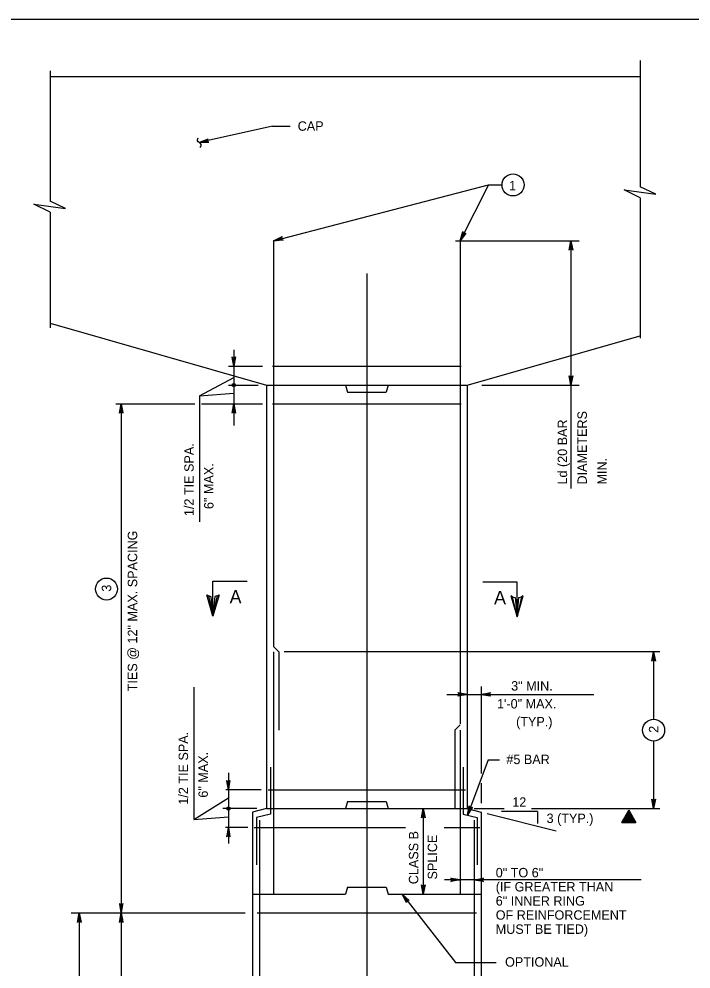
# Model space of a CAD drawing. Extents: x 646165 to 651486, y 296916 to 299292.
# Drawn here: x 650043.7 to 650257.8, y 298380.6 to 298683.3 of the extents above; entities that cross this region are included whole.
import ezdxf

# ---------------------------------------------------------------- set-up
doc = ezdxf.new("R2010")
doc.units = 0
for name, color, linetype in [('1', 7, 'Continuous'), ('2', 7, 'Continuous'), ('50', 7, 'Continuous'), ('51', 7, 'Continuous'), ('52', 7, 'Continuous'), ('53', 7, 'Continuous'), ('54', 7, 'Continuous')]:
    doc.layers.add(name, color=color, linetype=linetype)

msp = doc.modelspace()

# ---------------------------------------------------------------- linework, layer by layer
at = {"layer": '1'}
for p, q in [((650105.44, 298504.11), (650116.37, 298504.11)), ((650105.44, 298493.05), (650105.44, 298504.11)), ((650202.41, 298503.85), (650191.49, 298503.85)), ((650202.41, 298492.78), (650202.41, 298503.85))]:
    msp.add_line(p, q, dxfattribs=at)
for points in [[(650106.92, 298499.47), (650106.07, 298499.23), (650105.44, 298493.05), (650106.92, 298499.47), (650107.43, 298499.8), (650105.44, 298493.05), (650104.89, 298499.22), (650104.05, 298499.45), (650105.44, 298493.05), (650103.49, 298499.8), (650104.05, 298499.45)], [(650200.94, 298499.2), (650201.79, 298498.96), (650202.41, 298492.78), (650200.94, 298499.2), (650200.42, 298499.53), (650202.41, 298492.78), (650202.97, 298498.95), (650203.8, 298499.18), (650202.41, 298492.78), (650204.36, 298499.53), (650203.8, 298499.18)]]:
    msp.add_lwpolyline(points, dxfattribs=at)
at = {"layer": '2'}
msp.add_line((649829.59, 298683.25), (650615.59, 298683.25), dxfattribs=at)
at = {"layer": '50'}
msp.add_line((650154.51, 298602.2), (650154.51, 298236.03), dxfattribs=at)
at = {"layer": '51'}
for p, q in [((650053.58, 298664.97), (650241.62, 298664.97)), ((650053.58, 298586.3), (650122.56, 298566.63)), ((650186.46, 298566.63), (650241.62, 298582.36)), ((650122.56, 298566.63), (650186.46, 298566.63)), ((650122.56, 298566.63), (650122.56, 298431.7)), ((650147.76, 298566.63), (650148.34, 298564.38)), ((650161.26, 298566.63), (650160.68, 298564.38)), ((650186.46, 298566.63), (650186.46, 298431.7)), ((650148.34, 298564.38), (650160.68, 298564.38)), ((650122.56, 298431.7), (650118.06, 298430.58)), ((650122.56, 298431.7), (650186.46, 298431.7)), ((650148.34, 298433.95), (650147.76, 298431.7)), ((650148.34, 298433.95), (650160.68, 298433.95)), ((650160.68, 298433.95), (650161.26, 298431.7)), ((650186.46, 298431.7), (650190.96, 298430.58)), ((650118.06, 298430.58), (650118.06, 298296.63)), ((650190.96, 298430.58), (650190.96, 298296.63)), ((650118.06, 298404.45), (650147.76, 298404.45)), ((650148.34, 298406.7), (650147.76, 298404.45)), ((650148.34, 298406.7), (650160.68, 298406.7)), ((650160.68, 298406.7), (650161.26, 298404.45)), ((650161.26, 298404.45), (650190.96, 298404.45))]:
    msp.add_line(p, q, dxfattribs=at)
at = {"layer": '52'}
for p, q in [((650241.62, 298669.99), (650241.62, 298629.76)), ((650053.58, 298666.75), (650053.58, 298625.21)), ((650124.47, 298649.16), (650101.14, 298643.86)), ((650124.47, 298649.16), (650130.06, 298649.16)), ((650124.81, 298612.63), (650193.25, 298630.39)), ((650193.25, 298630.39), (650184.21, 298612.63)), ((650193.25, 298630.39), (650197.58, 298630.39)), ((650241.62, 298626.25), (650241.62, 298581.59)), ((650053.58, 298621.69), (650053.58, 298584.86)), ((650182.75, 298612.63), (650222.19, 298612.63)), ((650219.55, 298612.63), (650219.55, 298533.69)), ((650112.12, 298577.88), (650112.12, 298553.76)), ((650110.46, 298572.63), (650121.22, 298572.63)), ((650101.17, 298563.18), (650112.12, 298569.05)), ((650110.46, 298566.63), (650119.93, 298566.63)), ((650191.13, 298566.63), (650222.19, 298566.63)), ((650101.17, 298563.18), (650112.12, 298564.02)), ((650101.17, 298563.18), (650101.17, 298523.1)), ((650074.5, 298560.63), (650099.68, 298560.63)), ((650076.27, 298560.63), (650076.27, 298299.7)), ((650101.81, 298560.63), (650121.22, 298560.63)), ((650247.88, 298481.7), (650128.12, 298481.7)), ((650245.88, 298481.7), (650245.88, 298460.2)), ((650099.44, 298470.42), (650099.44, 298428.26)), ((650179.95, 298468.09), (650226.79, 298468.09)), ((650190.96, 298470.58), (650190.96, 298442.92)), ((650245.88, 298453.2), (650245.88, 298431.7)), ((650193.18, 298447.21), (650186.6, 298429.57)), ((650193.18, 298447.21), (650196.79, 298447.21)), ((650110.4, 298443.08), (650110.4, 298420.61)), ((650120.81, 298437.7), (650109.55, 298437.7)), ((650190.96, 298439.77), (650190.96, 298433.48)), ((650099.44, 298428.26), (650110.4, 298435.12)), ((650119.41, 298431.7), (650108.62, 298431.7)), ((650172.49, 298431.7), (650172.49, 298404.45)), ((650188.72, 298431.7), (650198.25, 298431.7)), ((650206.99, 298431.7), (650247.88, 298431.7)), ((650099.44, 298428.26), (650110.4, 298429.1)), ((650192.84, 298430.11), (650214.87, 298424.6)), ((650208.84, 298430.82), (650197.38, 298430.82)), ((650208.84, 298430.82), (650208.84, 298426.99)), ((650116.58, 298425.7), (650109.47, 298425.7)), ((650241.86, 298409.02), (650179.3, 298409.02)), ((650165.77, 298404.45), (650182.77, 298382.66)), ((650060.29, 298398.45), (650115.76, 298398.45)), ((650062.91, 298398.45), (650062.91, 298274.96)), ((650182.77, 298382.66), (650195.67, 298382.66))]:
    msp.add_line(p, q, dxfattribs=at)
for points in [[(650101.14, 298643.86), (650103.92, 298645.07), (650103.83, 298644.97), (650103.74, 298644.86), (650103.7, 298644.75), (650103.66, 298644.64), (650103.67, 298644.54), (650103.68, 298644.44), (650103.71, 298644.34), (650103.75, 298644.25), (650103.83, 298644.17), (650103.91, 298644.08), (650104.04, 298644.03), (650104.17, 298643.98), (650101.14, 298643.86), (650104.04, 298644.03), (650103.91, 298644.08), (650101.14, 298643.86), (650103.83, 298644.17), (650103.75, 298644.25), (650101.14, 298643.86), (650103.71, 298644.34), (650103.68, 298644.44), (650101.14, 298643.86), (650103.67, 298644.54), (650103.66, 298644.64), (650101.14, 298643.86), (650103.7, 298644.75), (650103.74, 298644.86), (650101.14, 298643.86), (650103.83, 298644.97)], [(650241.62, 298626.25), (650236.44, 298628.78), (650246.59, 298627.4), (650241.62, 298629.76)], [(650053.58, 298621.69), (650048.39, 298624.23), (650058.54, 298622.85), (650053.58, 298625.21)], [(650124.81, 298612.63), (650127.56, 298613.92), (650127.38, 298613.71), (650127.31, 298613.49), (650127.33, 298613.29), (650127.41, 298613.1), (650127.58, 298612.94), (650127.84, 298612.84), (650124.81, 298612.63), (650127.58, 298612.94), (650127.41, 298613.1), (650124.81, 298612.63), (650127.33, 298613.29), (650127.31, 298613.49), (650124.81, 298612.63), (650127.38, 298613.71)], [(650184.21, 298612.63), (650185.07, 298615.55), (650185.08, 298615.41), (650185.1, 298615.27), (650185.17, 298615.17), (650185.23, 298615.07), (650185.31, 298615.01), (650185.39, 298614.95), (650185.49, 298614.92), (650185.58, 298614.89), (650185.7, 298614.9), (650185.82, 298614.91), (650185.94, 298614.97), (650186.06, 298615.04), (650184.21, 298612.63), (650185.94, 298614.97), (650185.82, 298614.91), (650184.21, 298612.63), (650185.7, 298614.9), (650185.58, 298614.89), (650184.21, 298612.63), (650185.49, 298614.92), (650185.39, 298614.95), (650184.21, 298612.63), (650185.31, 298615.01), (650185.23, 298615.07), (650184.21, 298612.63), (650185.17, 298615.17), (650185.1, 298615.27), (650184.21, 298612.63), (650185.08, 298615.41)], [(650219.55, 298612.63), (650220.11, 298609.65), (650220.03, 298609.77), (650219.95, 298609.88), (650219.85, 298609.94), (650219.75, 298610), (650219.65, 298610.02), (650219.55, 298610.03), (650219.45, 298610.02), (650219.35, 298610), (650219.25, 298609.94), (650219.15, 298609.88), (650219.07, 298609.77), (650219, 298609.65), (650219.55, 298612.63), (650219.07, 298609.77), (650219.15, 298609.88), (650219.55, 298612.63), (650219.25, 298609.94), (650219.35, 298610), (650219.55, 298612.63), (650219.45, 298610.02), (650219.55, 298610.03), (650219.55, 298612.63), (650219.65, 298610.02), (650219.75, 298610), (650219.55, 298612.63), (650219.85, 298609.94), (650219.95, 298609.88), (650219.55, 298612.63), (650220.03, 298609.77)], [(650112.12, 298572.63), (650111.56, 298575.61), (650111.64, 298575.49), (650111.72, 298575.38), (650111.82, 298575.32), (650111.92, 298575.26), (650112.02, 298575.24), (650112.12, 298575.23), (650112.22, 298575.24), (650112.32, 298575.26), (650112.42, 298575.32), (650112.52, 298575.38), (650112.6, 298575.49), (650112.68, 298575.61), (650112.12, 298572.63), (650112.6, 298575.49), (650112.52, 298575.38), (650112.12, 298572.63), (650112.42, 298575.32), (650112.32, 298575.26), (650112.12, 298572.63), (650112.22, 298575.24), (650112.12, 298575.23), (650112.12, 298572.63), (650112.02, 298575.24), (650111.92, 298575.26), (650112.12, 298572.63), (650111.82, 298575.32), (650111.72, 298575.38), (650112.12, 298572.63), (650111.64, 298575.49)], [(650219.55, 298566.63), (650219, 298569.61), (650219.07, 298569.49), (650219.15, 298569.38), (650219.25, 298569.32), (650219.35, 298569.26), (650219.45, 298569.24), (650219.55, 298569.23), (650219.65, 298569.24), (650219.75, 298569.26), (650219.85, 298569.32), (650219.95, 298569.38), (650220.03, 298569.49), (650220.11, 298569.61), (650219.55, 298566.63), (650220.03, 298569.49), (650219.95, 298569.38), (650219.55, 298566.63), (650219.85, 298569.32), (650219.75, 298569.26), (650219.55, 298566.63), (650219.65, 298569.24), (650219.55, 298569.23), (650219.55, 298566.63), (650219.45, 298569.24), (650219.35, 298569.26), (650219.55, 298566.63), (650219.25, 298569.32), (650219.15, 298569.38), (650219.55, 298566.63), (650219.07, 298569.49)], [(650076.27, 298560.63), (650076.82, 298557.64), (650076.74, 298557.76), (650076.67, 298557.87), (650076.57, 298557.93), (650076.47, 298557.99), (650076.37, 298558.01), (650076.27, 298558.03), (650076.17, 298558.01), (650076.07, 298557.99), (650075.97, 298557.93), (650075.87, 298557.87), (650075.79, 298557.76), (650075.71, 298557.64), (650076.27, 298560.63), (650075.79, 298557.76), (650075.87, 298557.87), (650076.27, 298560.63), (650075.97, 298557.93), (650076.07, 298557.99), (650076.27, 298560.63), (650076.17, 298558.01), (650076.27, 298558.03), (650076.27, 298560.63), (650076.37, 298558.01), (650076.47, 298557.99), (650076.27, 298560.63), (650076.57, 298557.93), (650076.67, 298557.87), (650076.27, 298560.63), (650076.74, 298557.76)], [(650112.12, 298560.63), (650112.68, 298557.64), (650112.6, 298557.76), (650112.52, 298557.87), (650112.42, 298557.93), (650112.32, 298557.99), (650112.22, 298558.01), (650112.12, 298558.03), (650112.02, 298558.01), (650111.92, 298557.99), (650111.82, 298557.93), (650111.72, 298557.87), (650111.64, 298557.76), (650111.56, 298557.64), (650112.12, 298560.63), (650111.64, 298557.76), (650111.72, 298557.87), (650112.12, 298560.63), (650111.82, 298557.93), (650111.92, 298557.99), (650112.12, 298560.63), (650112.02, 298558.01), (650112.12, 298558.03), (650112.12, 298560.63), (650112.22, 298558.01), (650112.32, 298557.99), (650112.12, 298560.63), (650112.42, 298557.93), (650112.52, 298557.87), (650112.12, 298560.63), (650112.6, 298557.76)], [(650245.88, 298481.7), (650246.43, 298478.72), (650246.36, 298478.84), (650246.28, 298478.95), (650246.18, 298479.01), (650246.08, 298479.07), (650245.98, 298479.09), (650245.88, 298479.1), (650245.78, 298479.09), (650245.68, 298479.07), (650245.58, 298479.01), (650245.48, 298478.95), (650245.4, 298478.84), (650245.32, 298478.72), (650245.88, 298481.7), (650245.4, 298478.84), (650245.48, 298478.95), (650245.88, 298481.7), (650245.58, 298479.01), (650245.68, 298479.07), (650245.88, 298481.7), (650245.78, 298479.09), (650245.88, 298479.1), (650245.88, 298481.7), (650245.98, 298479.09), (650246.08, 298479.07), (650245.88, 298481.7), (650246.18, 298479.01), (650246.28, 298478.95), (650245.88, 298481.7), (650246.36, 298478.84)], [(650186.46, 298468.09), (650183.48, 298467.53), (650183.59, 298467.61), (650183.71, 298467.69), (650183.77, 298467.79), (650183.83, 298467.89), (650183.84, 298467.99), (650183.86, 298468.09), (650183.84, 298468.19), (650183.83, 298468.29), (650183.77, 298468.39), (650183.71, 298468.49), (650183.59, 298468.57), (650183.48, 298468.65), (650186.46, 298468.09), (650183.59, 298468.57), (650183.71, 298468.49), (650186.46, 298468.09), (650183.77, 298468.39), (650183.83, 298468.29), (650186.46, 298468.09), (650183.84, 298468.19), (650183.86, 298468.09), (650186.46, 298468.09), (650183.84, 298467.99), (650183.83, 298467.89), (650186.46, 298468.09), (650183.77, 298467.79), (650183.71, 298467.69), (650186.46, 298468.09), (650183.59, 298467.61)], [(650190.96, 298468.09), (650193.94, 298468.65), (650193.83, 298468.57), (650193.71, 298468.49), (650193.65, 298468.39), (650193.6, 298468.29), (650193.58, 298468.19), (650193.56, 298468.09), (650193.58, 298467.99), (650193.6, 298467.89), (650193.65, 298467.79), (650193.71, 298467.69), (650193.83, 298467.61), (650193.94, 298467.53), (650190.96, 298468.09), (650193.83, 298467.61), (650193.71, 298467.69), (650190.96, 298468.09), (650193.65, 298467.79), (650193.6, 298467.89), (650190.96, 298468.09), (650193.58, 298467.99), (650193.56, 298468.09), (650190.96, 298468.09), (650193.58, 298468.19), (650193.6, 298468.29), (650190.96, 298468.09), (650193.65, 298468.39), (650193.71, 298468.49), (650190.96, 298468.09), (650193.83, 298468.57)], [(650110.4, 298437.7), (650110.96, 298440.69), (650110.88, 298440.57), (650110.8, 298440.46), (650110.7, 298440.4), (650110.6, 298440.34), (650110.5, 298440.32), (650110.4, 298440.3), (650110.3, 298440.32), (650110.2, 298440.34), (650110.1, 298440.4), (650110, 298440.46), (650109.92, 298440.57), (650109.84, 298440.69), (650110.4, 298437.7), (650109.92, 298440.57), (650110, 298440.46), (650110.4, 298437.7), (650110.1, 298440.4), (650110.2, 298440.34), (650110.4, 298437.7), (650110.3, 298440.32), (650110.4, 298440.3), (650110.4, 298437.7), (650110.5, 298440.32), (650110.6, 298440.34), (650110.4, 298437.7), (650110.7, 298440.4), (650110.8, 298440.46), (650110.4, 298437.7), (650110.88, 298440.57)], [(650245.88, 298431.7), (650245.32, 298434.69), (650245.4, 298434.57), (650245.48, 298434.46), (650245.58, 298434.4), (650245.68, 298434.34), (650245.78, 298434.32), (650245.88, 298434.3), (650245.98, 298434.32), (650246.08, 298434.34), (650246.18, 298434.4), (650246.28, 298434.46), (650246.36, 298434.57), (650246.43, 298434.69), (650245.88, 298431.7), (650246.36, 298434.57), (650246.28, 298434.46), (650245.88, 298431.7), (650246.18, 298434.4), (650246.08, 298434.34), (650245.88, 298431.7), (650245.98, 298434.32), (650245.88, 298434.3), (650245.88, 298431.7), (650245.78, 298434.32), (650245.68, 298434.34), (650245.88, 298431.7), (650245.58, 298434.4), (650245.48, 298434.46), (650245.88, 298431.7), (650245.4, 298434.57)], [(650172.49, 298431.7), (650173.05, 298428.72), (650172.89, 298428.95), (650172.69, 298429.07), (650172.49, 298429.1), (650172.29, 298429.07), (650172.09, 298428.95), (650171.94, 298428.72), (650172.49, 298431.7), (650172.09, 298428.95), (650172.29, 298429.07), (650172.49, 298431.7), (650172.49, 298429.1), (650172.69, 298429.07), (650172.49, 298431.7), (650172.89, 298428.95)], [(650186.6, 298429.57), (650187.12, 298432.56), (650187.19, 298432.29), (650187.33, 298432.11), (650187.51, 298432.01), (650187.71, 298431.97), (650187.94, 298432.01), (650188.17, 298432.17), (650186.6, 298429.57), (650187.94, 298432.01), (650187.71, 298431.97), (650186.6, 298429.57), (650187.51, 298432.01), (650187.33, 298432.11), (650186.6, 298429.57), (650187.19, 298432.29)], [(650110.4, 298425.7), (650109.84, 298422.72), (650109.92, 298422.84), (650110, 298422.95), (650110.1, 298423.01), (650110.2, 298423.07), (650110.3, 298423.09), (650110.4, 298423.1), (650110.5, 298423.09), (650110.6, 298423.07), (650110.7, 298423.01), (650110.8, 298422.95), (650110.88, 298422.84), (650110.96, 298422.72), (650110.4, 298425.7), (650110.88, 298422.84), (650110.8, 298422.95), (650110.4, 298425.7), (650110.7, 298423.01), (650110.6, 298423.07), (650110.4, 298425.7), (650110.5, 298423.09), (650110.4, 298423.1), (650110.4, 298425.7), (650110.3, 298423.09), (650110.2, 298423.07), (650110.4, 298425.7), (650110.1, 298423.01), (650110, 298422.95), (650110.4, 298425.7), (650109.92, 298422.84)], [(650172.49, 298404.45), (650171.94, 298407.44), (650172.09, 298407.21), (650172.29, 298407.09), (650172.49, 298407.05), (650172.69, 298407.09), (650172.89, 298407.21), (650173.05, 298407.44), (650172.49, 298404.45), (650172.89, 298407.21), (650172.69, 298407.09), (650172.49, 298404.45), (650172.49, 298407.05), (650172.29, 298407.09), (650172.49, 298404.45), (650172.09, 298407.21)], [(650184.21, 298409.02), (650181.23, 298408.46), (650181.46, 298408.62), (650181.58, 298408.82), (650181.61, 298409.02), (650181.58, 298409.22), (650181.46, 298409.42), (650181.23, 298409.58), (650184.21, 298409.02), (650181.46, 298409.42), (650181.58, 298409.22), (650184.21, 298409.02), (650181.61, 298409.02), (650181.58, 298408.82), (650184.21, 298409.02), (650181.46, 298408.62)], [(650188.71, 298409.02), (650191.69, 298409.58), (650191.46, 298409.42), (650191.35, 298409.22), (650191.31, 298409.02), (650191.35, 298408.82), (650191.46, 298408.62), (650191.69, 298408.46), (650188.71, 298409.02), (650191.46, 298408.62), (650191.35, 298408.82), (650188.71, 298409.02), (650191.31, 298409.02), (650191.35, 298409.22), (650188.71, 298409.02), (650191.46, 298409.42)], [(650165.77, 298404.45), (650168.04, 298402.45), (650167.78, 298402.53), (650167.55, 298402.5), (650167.37, 298402.4), (650167.23, 298402.25), (650167.15, 298402.04), (650167.16, 298401.76), (650165.77, 298404.45), (650167.15, 298402.04), (650167.23, 298402.25), (650165.77, 298404.45), (650167.37, 298402.4), (650167.55, 298402.5), (650165.77, 298404.45), (650167.78, 298402.53)], [(650076.27, 298398.45), (650076.82, 298401.44), (650076.74, 298401.32), (650076.67, 298401.21), (650076.57, 298401.15), (650076.47, 298401.09), (650076.37, 298401.07), (650076.27, 298401.05), (650076.17, 298401.07), (650076.07, 298401.09), (650075.97, 298401.15), (650075.87, 298401.21), (650075.79, 298401.32), (650075.71, 298401.44), (650076.27, 298398.45), (650075.79, 298401.32), (650075.87, 298401.21), (650076.27, 298398.45), (650075.97, 298401.15), (650076.07, 298401.09), (650076.27, 298398.45), (650076.17, 298401.07), (650076.27, 298401.05), (650076.27, 298398.45), (650076.37, 298401.07), (650076.47, 298401.09), (650076.27, 298398.45), (650076.57, 298401.15), (650076.67, 298401.21), (650076.27, 298398.45), (650076.74, 298401.32)], [(650062.91, 298398.45), (650063.47, 298395.47), (650063.39, 298395.59), (650063.31, 298395.7), (650063.21, 298395.76), (650063.11, 298395.82), (650063.01, 298395.84), (650062.91, 298395.85), (650062.81, 298395.84), (650062.71, 298395.82), (650062.61, 298395.76), (650062.51, 298395.7), (650062.43, 298395.59), (650062.35, 298395.47), (650062.91, 298398.45), (650062.43, 298395.59), (650062.51, 298395.7), (650062.91, 298398.45), (650062.61, 298395.76), (650062.71, 298395.82), (650062.91, 298398.45), (650062.81, 298395.84), (650062.91, 298395.85), (650062.91, 298398.45), (650063.01, 298395.84), (650063.11, 298395.82), (650062.91, 298398.45), (650063.21, 298395.76), (650063.31, 298395.7), (650062.91, 298398.45), (650063.39, 298395.59)], [(650076.27, 298398.45), (650076.82, 298395.47), (650076.74, 298395.59), (650076.67, 298395.7), (650076.57, 298395.76), (650076.47, 298395.82), (650076.37, 298395.84), (650076.27, 298395.85), (650076.17, 298395.84), (650076.07, 298395.82), (650075.97, 298395.76), (650075.87, 298395.7), (650075.79, 298395.59), (650075.71, 298395.47), (650076.27, 298398.45), (650075.79, 298395.59), (650075.87, 298395.7), (650076.27, 298398.45), (650075.97, 298395.76), (650076.07, 298395.82), (650076.27, 298398.45), (650076.17, 298395.84), (650076.27, 298395.85), (650076.27, 298398.45), (650076.37, 298395.84), (650076.47, 298395.82), (650076.27, 298398.45), (650076.57, 298395.76), (650076.67, 298395.7), (650076.27, 298398.45), (650076.74, 298395.59)]]:
    msp.add_lwpolyline(points, dxfattribs=at)
for centre, radius in [((650201.08, 298630.39), 3.5), ((650112.12, 298566.63), 0.533), ((650112.12, 298566.63), 0.267), ((650071.56, 298501.66), 3.5), ((650245.88, 298456.7), 3.5), ((650110.4, 298431.7), 0.533), ((650110.4, 298431.7), 0.267)]:
    msp.add_circle(centre, radius, dxfattribs=at)
msp.add_spline([(650101.45, 298642.33), (650101.71, 298643.28), (650100.56, 298644.45), (650100.78, 298645.37)], degree=3, dxfattribs=at)
at = {"layer": '53'}
msp.add_line((650237.97, 298428.58), (650237.97, 298428.58), dxfattribs=at)
for points in [[(650235.74, 298427.29), (650240.2, 298427.29), (650237.97, 298431.16), (650235.74, 298427.29)], [(650235.74, 298427.29), (650237.97, 298431.16), (650240.2, 298427.29), (650235.74, 298427.29), (650237.96, 298431.04), (650240.13, 298427.35), (650235.83, 298427.34), (650237.97, 298430.93), (650240.04, 298427.4), (650235.93, 298427.39), (650237.98, 298430.81), (650239.94, 298427.47), (650236.03, 298427.44), (650237.97, 298430.7), (650239.84, 298427.52), (650236.14, 298427.51), (650237.98, 298430.56), (650239.73, 298427.58), (650236.26, 298427.58), (650237.97, 298430.42), (650239.63, 298427.64), (650236.36, 298427.64), (650237.97, 298430.29), (650239.52, 298427.71), (650236.47, 298427.7), (650237.97, 298430.16), (650239.4, 298427.78), (650236.57, 298427.76), (650237.98, 298430.04), (650239.26, 298427.84), (650236.69, 298427.83), (650237.98, 298429.91), (650239.13, 298427.93), (650236.81, 298427.89), (650237.98, 298429.76), (650239.01, 298428.01), (650236.92, 298427.95), (650237.98, 298429.63), (650238.89, 298428.08), (650237.06, 298428.02), (650237.98, 298429.5), (650238.78, 298428.14), (650237.19, 298428.08), (650237.98, 298429.35), (650238.65, 298428.21), (650237.33, 298428.15), (650237.98, 298429.22), (650238.52, 298428.28), (650237.43, 298428.22), (650237.97, 298429.09), (650238.39, 298428.35), (650237.56, 298428.28), (650237.97, 298428.97), (650238.29, 298428.4), (650237.66, 298428.34), (650237.97, 298428.84), (650238.19, 298428.46), (650237.77, 298428.39), (650237.98, 298428.72), (650238.1, 298428.5), (650237.88, 298428.47), (650237.97, 298428.58), (650240.19, 298427.31), (650237.97, 298428.58), (650237.97, 298431.13), (650237.98, 298428.57), (650235.75, 298427.3)]]:
    msp.add_lwpolyline(points, dxfattribs=at)
at = {"layer": '54'}
for p, q in [((650124.81, 298612.63), (650124.81, 298483.37)), ((650184.21, 298612.63), (650184.21, 298458.67)), ((650124.41, 298572.63), (650184.61, 298572.63)), ((650124.41, 298560.63), (650184.61, 298560.63)), ((650126.48, 298481.7), (650124.81, 298483.37)), ((650124.81, 298481.7), (650124.81, 298404.45)), ((650126.48, 298481.7), (650126.48, 298456.7)), ((650182.54, 298456.7), (650184.21, 298458.37)), ((650182.54, 298456.7), (650182.54, 298431.7)), ((650184.21, 298456.7), (650184.21, 298404.45)), ((650123.81, 298444.95), (650123.81, 298429.95)), ((650185.21, 298444.95), (650185.21, 298429.95)), ((650123.06, 298437.7), (650185.96, 298437.7)), ((650123.81, 298429.95), (650119.31, 298428.83)), ((650119.31, 298428.83), (650119.31, 298413.83)), ((650185.21, 298429.95), (650189.71, 298428.83)), ((650189.71, 298428.83), (650189.71, 298413.83)), ((650118.56, 298425.7), (650166.81, 298425.7)), ((650120.31, 298427.99), (650120.31, 298249.41)), ((650179.19, 298425.7), (650190.46, 298425.7)), ((650188.71, 298427.99), (650188.71, 298249.41)), ((650119.56, 298398.45), (650189.46, 298398.45))]:
    msp.add_line(p, q, dxfattribs=at)

# ---------------------------------------------------------------- texts
at = {"layer": '1'}
for p in [(650110.8, 298497.1), (650195.05, 298496.83)]:
    msp.add_text('A', height=4.23, dxfattribs=at).set_placement(p)
at = {"layer": '53'}
for s, p in [('CAP', (650132.48, 298647.65)), ('1', (650199.81, 298628.67)), ('3" MIN.', (650200.49, 298469.3)), ('1\'-0" MAX.', (650195.99, 298463.6)), ('(TYP.)', (650202.06, 298457.9)), ('#5 BAR', (650198.97, 298445.88)), ('12', (650200.85, 298432.3)), ('3 (TYP.)', (650211.77, 298427.12)), ('0" TO 6"', (650195.58, 298409.81)), ('(IF GREATER THAN', (650195.58, 298405.31)), ('6" INNER RING', (650195.58, 298400.81)), ('OF REINFORCEMENT', (650195.58, 298396.31)), ('MUST BE TIED)', (650195.58, 298391.81)), ('OPTIONAL', (650198.55, 298381.36))]:
    msp.add_text(s, height=3, dxfattribs=at).set_placement(p)
for s, p in [('DIAMETERS', (650224.61, 298534.95)), ('Ld (20 BAR ', (650218.31, 298534.95)), ('1/2 TIE SPA.', (650099.35, 298524.9)), ('  6" MAX.', (650105.65, 298524.9)), ('MIN.', (650230.91, 298534.95)), ('TIES @ 12" MAX. SPACING', (650081.34, 298469.08)), ('3', (650073.06, 298500.81)), ('2', (650247.38, 298455.85)), ('1/2 TIE SPA.', (650097.55, 298432.96)), ('  6" MAX.', (650103.85, 298432.96)), ('CLASS B', (650170.9, 298407.62)), ('SPLICE', (650176.9, 298409.13))]:
    msp.add_text(s, height=3, rotation=90, dxfattribs=at).set_placement(p)

doc.saveas('drawing.dxf')
